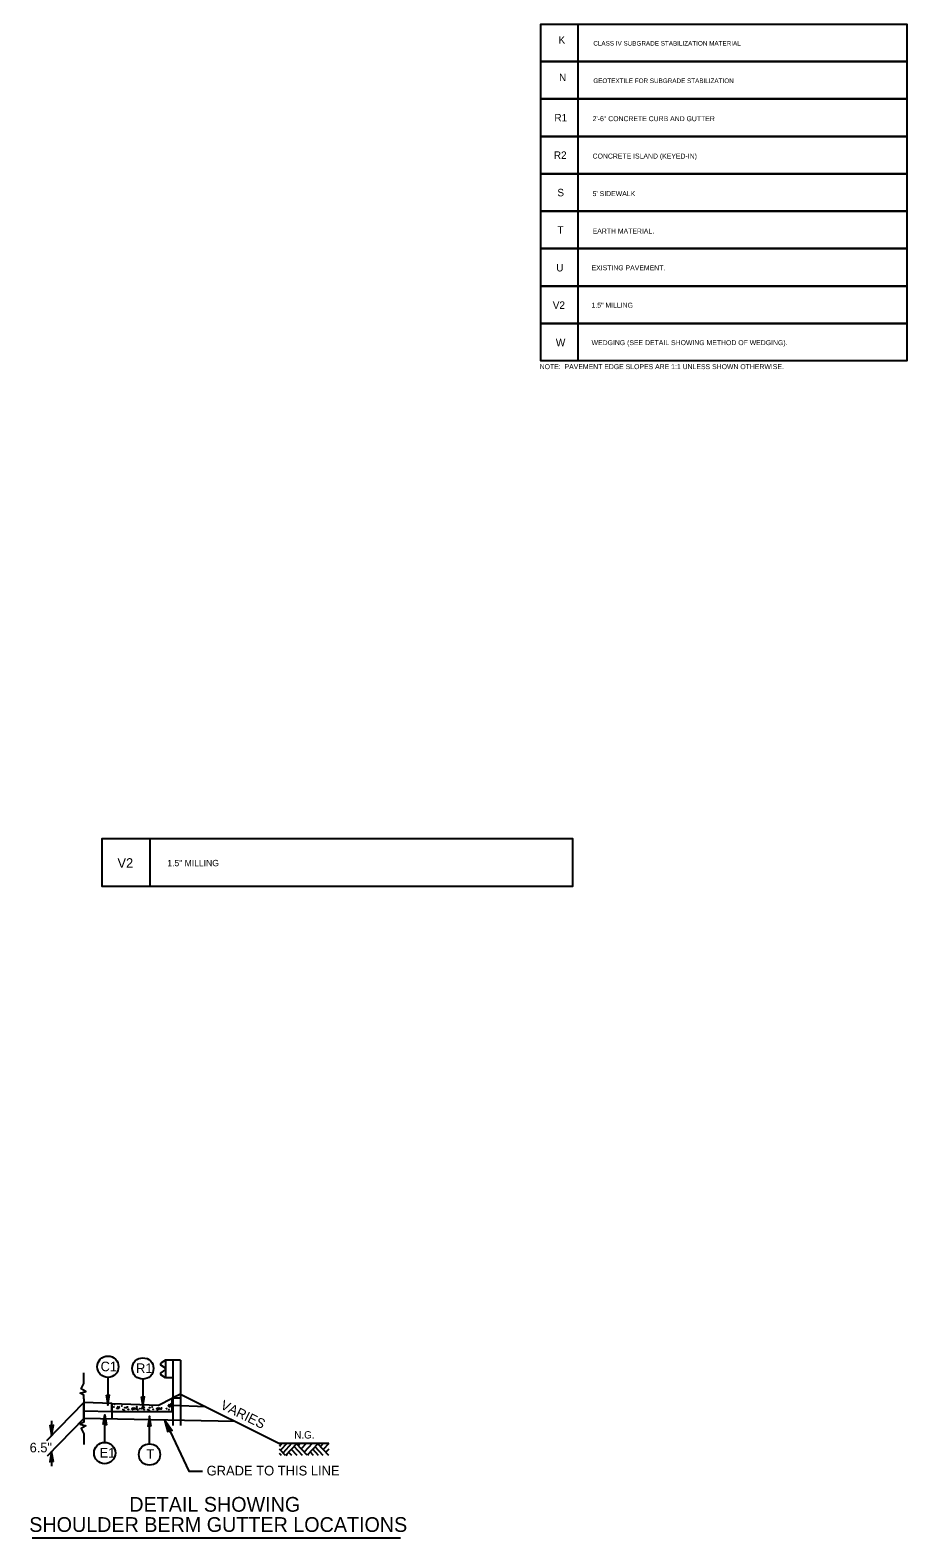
# Model space of a CAD drawing. Extents: x 1901670 to 1902225, y 193498 to 194278.
# Drawn here: x 1902135.7 to 1902225.1, y 194002.7 to 194156.6 of the extents above; entities that cross this region are included whole.
import ezdxf

# ---------------------------------------------------------------- set-up
doc = ezdxf.new("R2010")
doc.units = 0
for name, color, linetype in [('Old_Level_1', 7, 'Continuous'), ('Old_Level_19', 7, 'Continuous'), ('Old_Level_20', 7, 'Continuous'), ('Old_Level_21', 7, 'Continuous'), ('Prop Pavement Schedule Description CELL', 7, 'Continuous'), ('Typical Terminator CELL', 7, 'Continuous')]:
    doc.layers.add(name, color=color, linetype=linetype)

# ---------------------------------------------------------------- blocks, each defined once
blk = doc.blocks.new('TERMINATOR')
at = {"layer": 'Typical Terminator CELL'}
blk.add_lwpolyline([(-0.469, 0.081), (0, 0), (-0.471, -0.083), (-0.411, 0)], close=True, dxfattribs=at)

msp = doc.modelspace()

# ---------------------------------------------------------------- linework, layer by layer
at = {"layer": 'Old_Level_1'}
for p, q in [((1902149.46, 194020.88), (1902149.01, 194020.56)), ((1902149.46, 194020.05), (1902149.01, 194020.37)), ((1902149.46, 194019.91), (1902149.01, 194019.59)), ((1902149.46, 194019.08), (1902149.01, 194019.39)), ((1902149.46, 194020.88), (1902149.46, 194019.08)), ((1902151.01, 194020.88), (1902149.46, 194020.88)), ((1902149.46, 194019.98), (1902149.46, 194020.05)), ((1902149.46, 194019.98), (1902149.46, 194019.91)), ((1902150.23, 194020.88), (1902150.23, 194017.02)), ((1902151.01, 194020.88), (1902151.01, 194017.02)), ((1902143.59, 194019.12), (1902143.59, 194016.3)), ((1902147.16, 194018.94), (1902147.16, 194016.12)), ((1902150.23, 194019.08), (1902149.46, 194019.08)), ((1902141.13, 194016.57), (1902137.33, 194012.63)), ((1902141.14, 194014.96), (1902141.13, 194016.57)), ((1902144.01, 194016.46), (1902141.13, 194016.57)), ((1902144.01, 194016.46), (1902144.01, 194016.46)), ((1902144.01, 194015.62), (1902144.01, 194016.44)), ((1902144.01, 194016.44), (1902144.01, 194014.88)), ((1902144.04, 194016.46), (1902148.75, 194016.29)), ((1902148.75, 194016.29), (1902150.15, 194016.99)), ((1902149.76, 194016.31), (1902149.8, 194016.13)), ((1902150.08, 194016.22), (1902149.76, 194016.31)), ((1902151.01, 194017.42), (1902150.15, 194016.99)), ((1902150.15, 194015.62), (1902150.15, 194016.99)), ((1902150.23, 194017.02), (1902151.01, 194017.02)), ((1902150.23, 194017.02), (1902150.23, 194014.22)), ((1902151.01, 194017.42), (1902161.1, 194012.36)), ((1902151.01, 194017.02), (1902151.01, 194014.22)), ((1902141.13, 194014.94), (1902137.41, 194011.09)), ((1902144.02, 194015.61), (1902141.13, 194015.67)), ((1902156.56, 194014.63), (1902141.13, 194014.94)), ((1902143.27, 194012.49), (1902143.27, 194015.31)), ((1902150.15, 194015.62), (1902144.01, 194015.62)), ((1902144.5, 194015.92), (1902144.67, 194016.17)), ((1902144.74, 194015.94), (1902144.5, 194015.92)), ((1902144.67, 194016.17), (1902144.74, 194015.94)), ((1902146.05, 194015.82), (1902146.18, 194016.05)), ((1902146.39, 194015.9), (1902146.05, 194015.82)), ((1902146.18, 194016.05), (1902146.39, 194015.9)), ((1902147.04, 194015.92), (1902147.21, 194016.17)), ((1902147.28, 194015.94), (1902147.04, 194015.92)), ((1902147.21, 194016.17), (1902147.28, 194015.94)), ((1902147.84, 194012.34), (1902147.84, 194015.16)), ((1902148.59, 194015.82), (1902148.72, 194016.05)), ((1902148.92, 194015.9), (1902148.59, 194015.82)), ((1902148.72, 194016.05), (1902148.92, 194015.9)), ((1902149.8, 194016.13), (1902150.08, 194016.22)), ((1902153.6, 194016.12), (1902150.15, 194016.24)), ((1902137.85, 194014.68), (1902137.85, 194013.18)), ((1902150.31, 194014.76), (1902150.29, 194014.76)), ((1902161.36, 194012.36), (1902161.1, 194012.08)), ((1902161.71, 194011.16), (1902161.1, 194011.81)), ((1902161.84, 194012.36), (1902161.22, 194011.69)), ((1902162.34, 194012.36), (1902161.47, 194011.42)), ((1902162.83, 194012.35), (1902161.71, 194011.16)), ((1902162.9, 194011.14), (1902162.3, 194011.79)), ((1902163.46, 194011.14), (1902162.58, 194012.09)), ((1902163.93, 194011.17), (1902162.83, 194012.35)), ((1902163.22, 194012.36), (1902163.02, 194012.14)), ((1902163.83, 194012.36), (1902163.33, 194011.82)), ((1902164.43, 194012.36), (1902163.62, 194011.49)), ((1902165.02, 194012.34), (1902163.93, 194011.17)), ((1902165.1, 194011.14), (1902164.5, 194011.79)), ((1902165.57, 194011.14), (1902164.74, 194012.04)), ((1902166.13, 194011.14), (1902165.02, 194012.34)), ((1902165.57, 194012.36), (1902165.29, 194012.05)), ((1902166.13, 194012.36), (1902165.57, 194011.75)), ((1902166.13, 194011.81), (1902165.82, 194011.48)), ((1902137.85, 194011.55), (1902137.85, 194010.05)), ((1902161.3, 194011.14), (1902161.1, 194011.36)), ((1902161.91, 194011.14), (1902161.8, 194011.26)), ((1902162.35, 194011.14), (1902162.03, 194011.5)), ((1902164.11, 194011.14), (1902164.01, 194011.26)), ((1902164.58, 194011.14), (1902164.24, 194011.51)), ((1902135.87, 194002.74), (1902173.46, 194002.74))]:
    msp.add_line(p, q, dxfattribs=at)
for points in [[(1902141.13, 194016.94), (1902141.13, 194017.32), (1902140.78, 194017.51), (1902141.34, 194017.69), (1902140.86, 194017.96), (1902141.13, 194018.49), (1902141.13, 194019.6)], [(1902141.13, 194016.94), (1902141.13, 194014.54), (1902140.78, 194014.35), (1902141.34, 194014.17), (1902140.86, 194013.9), (1902141.13, 194013.37), (1902141.13, 194012.26)], [(1902149.41, 194014.77), (1902151.86, 194009.55), (1902153.25, 194009.55)], [(1902166.13, 194012.36), (1902161.1, 194012.36)]]:
    msp.add_lwpolyline(points, dxfattribs=at)
for points in [[(1902143.42, 194017.31), (1902143.59, 194016.3), (1902143.77, 194017.31), (1902143.59, 194017.18)], [(1902146.99, 194017.13), (1902147.16, 194016.12), (1902147.34, 194017.14), (1902147.16, 194017.01)], [(1902143.1, 194014.3), (1902143.27, 194015.31), (1902143.45, 194014.29), (1902143.27, 194014.42)], [(1902148.01, 194014.15), (1902147.84, 194015.16), (1902147.66, 194014.15), (1902147.84, 194014.27)], [(1902149.75, 194013.53), (1902149.41, 194014.77), (1902150.16, 194013.71), (1902149.88, 194013.76)]]:
    msp.add_lwpolyline(points, close=True, dxfattribs=at)
for centre, radius in [((1902143.59, 194020.21), 1.09), ((1902147.16, 194020.03), 1.09), ((1902144.27, 194016.36), 0.0163), ((1902150.02, 194016.4), 0.0163), ((1902144.2, 194016.1), 0.0163), ((1902145.02, 194016.2), 0.0163), ((1902145.14, 194015.84), 0.0163), ((1902145.25, 194015.77), 0.0163), ((1902145.32, 194016.03), 0.0163), ((1902145.47, 194016.03), 0.0163), ((1902145.58, 194016.09), 0.0163), ((1902145.67, 194015.85), 0.0163), ((1902146.07, 194015.93), 0.0163), ((1902146.48, 194015.9), 0.0163), ((1902146.52, 194016), 0.0163), ((1902146.54, 194016.12), 0.0163), ((1902146.65, 194015.83), 0.0163), ((1902146.85, 194015.93), 0.0163), ((1902147.04, 194015.94), 0.0163), ((1902147.28, 194015.84), 0.0163), ((1902147.68, 194015.84), 0.0163), ((1902147.79, 194015.77), 0.0163), ((1902147.86, 194016.03), 0.0163), ((1902148.11, 194016.09), 0.0163), ((1902148.21, 194015.85), 0.0163), ((1902148.6, 194015.93), 0.0163), ((1902148.66, 194015.73), 0.0163), ((1902149.02, 194015.9), 0.0163), ((1902149.06, 194016), 0.0163), ((1902149.58, 194015.94), 0.0163), ((1902149.82, 194015.84), 0.0163), ((1902143.27, 194011.4), 1.09), ((1902147.84, 194011.25), 1.09)]:
    msp.add_circle(centre, radius, dxfattribs=at)
for centre, radius, start, end in [((1902149.08, 194020.46), 0.12, 125.0059, 235.0366), ((1902149.08, 194019.49), 0.12, 125.0059, 235.0366), ((1902144.04, 194016.44), 0.0212, 87.952, 180)]:
    msp.add_arc(centre, radius, start, end, dxfattribs=at)
at = {"layer": 'Old_Level_19'}
for points in [[(1902191.59, 194145.79), (1902187.77, 194145.79), (1902187.77, 194149.61), (1902225.12, 194149.61), (1902225.12, 194145.79), (1902191.59, 194145.79), (1902191.59, 194149.61)], [(1902191.59, 194141.97), (1902187.77, 194141.97), (1902187.77, 194145.79), (1902225.12, 194145.79), (1902225.12, 194141.97), (1902191.59, 194141.97), (1902191.59, 194145.79)], [(1902191.59, 194138.15), (1902187.77, 194138.15), (1902187.77, 194141.97), (1902225.12, 194141.97), (1902225.12, 194138.15), (1902191.59, 194138.15), (1902191.59, 194141.97)], [(1902191.59, 194134.33), (1902187.77, 194134.33), (1902187.77, 194138.15), (1902225.12, 194138.15), (1902225.12, 194134.33), (1902191.59, 194134.33), (1902191.59, 194138.15)], [(1902191.59, 194130.51), (1902187.77, 194130.51), (1902187.77, 194134.33), (1902225.12, 194134.33), (1902225.12, 194130.51), (1902191.59, 194130.51), (1902191.59, 194134.33)], [(1902191.59, 194126.68), (1902187.77, 194126.68), (1902187.77, 194130.51), (1902225.12, 194130.51), (1902225.12, 194126.68), (1902191.59, 194126.68), (1902191.59, 194130.51)], [(1902191.59, 194122.86), (1902187.77, 194122.86), (1902187.77, 194126.68), (1902225.12, 194126.68), (1902225.12, 194122.86), (1902191.59, 194122.86), (1902191.59, 194126.68)], [(1902147.91, 194069.21), (1902143, 194069.21), (1902143, 194074.12), (1902191, 194074.12), (1902191, 194069.21), (1902147.91, 194069.21), (1902147.91, 194074.12)]]:
    msp.add_lwpolyline(points, dxfattribs=at)
at = {"layer": 'Prop Pavement Schedule Description CELL'}
for points in [[(1902191.59, 194153.43), (1902187.77, 194153.43), (1902187.77, 194157.25), (1902225.13, 194157.25), (1902225.13, 194153.43), (1902191.59, 194153.43), (1902191.59, 194157.25)], [(1902191.59, 194149.61), (1902187.77, 194149.61), (1902187.77, 194153.43), (1902225.13, 194153.43), (1902225.13, 194149.61), (1902191.59, 194149.61), (1902191.59, 194153.43)]]:
    msp.add_lwpolyline(points, dxfattribs=at)

# ---------------------------------------------------------------- block references
at = {"layer": 'Old_Level_1', "xscale": 2.2569975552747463, "yscale": -2.2569975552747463}
for p, rotation in [((1902137.85, 194013.18), -90), ((1902137.85, 194011.55), 90.00000000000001)]:
    msp.add_blockref('TERMINATOR', p, dxfattribs=dict(at, rotation=rotation))

# ---------------------------------------------------------------- texts
at = {"layer": 'Old_Level_1'}
for s, height, p in [('C1', 0.977, (1902142.85, 194019.75)), ('R1', 0.977, (1902146.47, 194019.57)), ('N.G.', 0.752, (1902162.61, 194012.88)), ('E1', 0.977, (1902142.75, 194010.94)), ('T', 0.977, (1902147.52, 194010.81)), ('GRADE TO THIS LINE', 0.9871, (1902153.67, 194009.11))]:
    msp.add_text(s, height=height, dxfattribs=at).set_placement(p)
for s, height, rotation, p in [('VARIES', 0.987, 333.8251, (1902155, 194015.97)), ('DETAIL SHOWING', 1.5047, 359.9999, (1902145.78, 194005.41)), ('SHOULDER BERM GUTTER LOCATIONS', 1.5047, 359.9999, (1902135.57, 194003.35))]:
    msp.add_text(s, height=height, rotation=rotation, dxfattribs=at).set_placement(p)
at = {"layer": 'Old_Level_20'}
msp.add_text('6.5"', height=0.977, dxfattribs=at).set_placement((1902135.61, 194011.47))
at = {"layer": 'Old_Level_21'}
for s, height, p in [('R1', 0.763, (1902189.16, 194147.31)), ('2\'-6" CONCRETE CURB AND GUTTER', 0.5082, (1902193.06, 194147.34)), ('R2', 0.763, (1902189.1, 194143.49)), ('CONCRETE ISLAND (KEYED-IN)', 0.5082, (1902193.06, 194143.52)), ('S', 0.763, (1902189.46, 194139.67)), ("5' SIDEWALK", 0.5082, (1902193.06, 194139.69)), ('T', 0.763, (1902189.46, 194135.85)), ('EARTH MATERIAL.', 0.5082, (1902193.06, 194135.87)), ('U', 0.763, (1902189.35, 194132)), ('EXISTING PAVEMENT.', 0.5082, (1902192.95, 194132.12)), ('V2', 0.763, (1902188.99, 194128.18)), ('1.5" MILLING', 0.5082, (1902192.95, 194128.3)), ('W', 0.763, (1902189.31, 194124.36)), ('WEDGING (SEE DETAIL SHOWING METHOD OF WEDGING).', 0.5082, (1902192.95, 194124.48)), ('NOTE:  PAVEMENT EDGE SLOPES ARE 1:1 UNLESS SHOWN OTHERWISE.', 0.5082, (1902187.66, 194122.03)), ('V2', 0.98, (1902144.57, 194071.13)), ('1.5" MILLING', 0.653, (1902149.66, 194071.29))]:
    msp.add_text(s, height=height, dxfattribs=at).set_placement(p)
at = {"layer": 'Prop Pavement Schedule Description CELL'}
for s, height, p in [('K', 0.763, (1902189.58, 194155.25)), ('CLASS IV SUBGRADE STABILIZATION MATERIAL', 0.4669, (1902193.13, 194155.05)), ('N', 0.763, (1902189.63, 194151.43)), ('GEOTEXTILE FOR SUBGRADE STABILIZATION', 0.4669, (1902193.13, 194151.23))]:
    msp.add_text(s, height=height, dxfattribs=at).set_placement(p)

doc.saveas('drawing.dxf')
